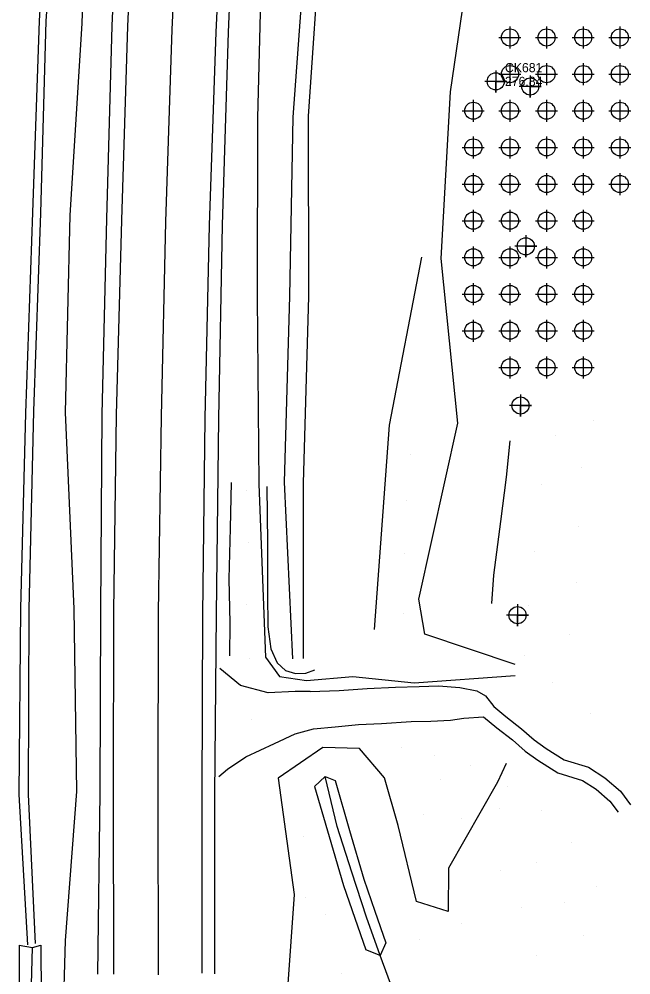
# Model space of a CAD drawing. Extents: x 1941547 to 1942851, y 663002 to 668358.
# Drawn here: x 1941926.1 to 1942093, y 667414.3 to 667675 of the extents above; entities that cross this region are included whole.
import ezdxf

# ---------------------------------------------------------------- set-up
doc = ezdxf.new("R2010")
doc.units = 0
for name, color, linetype in [('CTL GPS Vertical Cogo Elevation', 7, 'Continuous'), ('CTL NGS Vertical CELL', 7, 'Continuous'), ('Exist DTM Drainline Cogo Elevation', 7, 'Continuous'), ('Exist DTM QL2 LIDAR Elevation Point', 7, 'Continuous'), ('Exist Property Iron Pin Cogo Number', 7, 'Continuous'), ('Exist Roads EOP Cogo Point CELL', 7, 'Continuous'), ('Exist Roads EOT', 7, 'Continuous'), ('Exist Utilities Telephone UG Cable SUE LOS C Cogo Elevation', 7, 'Continuous'), ('Exist Utilities Telephone UG FO SUE LOS C Cogo Elevation', 7, 'Continuous'), ('PH Exist DTM Breakline', 7, 'Continuous'), ('PH Exist DTM Point', 7, 'Continuous')]:
    doc.layers.add(name, color=color, linetype=linetype)

msp = doc.modelspace()

# ---------------------------------------------------------------- linework, layer by layer
at = {"layer": 'CTL NGS Vertical CELL'}
for points in [[(1942024.37, 668012.57), (1942022.28, 667994.37), (1942017.39, 667944.52), (1942014.27, 667895.82), (1942009.92, 667846.63), (1942007.93, 667796.15), (1942005.97, 667746.35), (1942004.4, 667697.91), (1942000.78, 667648.26), (1941999.86, 667599.46), (1941998.39, 667548.71), (1942000.68, 667500.48)], [(1942026.8, 668012.52), (1942024.33, 667994.23), (1942019.53, 667944.62), (1942016.16, 667895.49), (1942012.43, 667846.36), (1942010.79, 667795.94), (1942008.34, 667746.43), (1942008.34, 667697.72), (1942004.96, 667648.49), (1942005.04, 667599.29), (1942003.6, 667548.44), (1942003.59, 667500.58)], [(1941930.54, 667422.84), (1941928.68, 667463.46), (1941928.78, 667514.02), (1941930.06, 667568.07), (1941931.99, 667622.09), (1941933.48, 667674.51), (1941937.26, 667726.95), (1941939.71, 667779.55), (1941943.19, 667828.89), (1941946.38, 667878.43), (1941949.61, 667928.57), (1941952.29, 667965.88), (1941953.97, 667997.88)], [(1941928.41, 667422.42), (1941926.07, 667463.45), (1941926.54, 667514.2), (1941927.95, 667567.47), (1941929.84, 667622.24), (1941931.61, 667674.49), (1941934.69, 667727.1), (1941937.88, 667779.66), (1941941.36, 667829.21), (1941944.43, 667878.58), (1941947.39, 667928.96), (1941950.55, 667966.21)]]:
    msp.add_lwpolyline(points, dxfattribs=at)
at = {"layer": 'Exist DTM Drainline Cogo Elevation'}
for points in [[(1942056.13, 667661.01), (1942056.13, 667655.01), (1942056.13, 667658.01), (1942059.13, 667658.01), (1942053.13, 667658.01)], [(1942056.13, 667661.01), (1942056.13, 667655.01), (1942056.13, 667658.01), (1942059.13, 667658.01), (1942053.13, 667658.01)], [(1942065.54, 667659.62), (1942065.54, 667653.62), (1942065.54, 667656.62), (1942068.54, 667656.62), (1942062.54, 667656.62)], [(1942064.32, 667616.02), (1942064.32, 667610.02), (1942064.32, 667613.02), (1942067.32, 667613.02), (1942061.32, 667613.02)], [(1942062.89, 667572.6), (1942062.89, 667566.6), (1942062.89, 667569.6), (1942065.89, 667569.6), (1942059.89, 667569.6)], [(1942062.08, 667515.39), (1942062.08, 667509.39), (1942062.08, 667512.39), (1942065.08, 667512.39), (1942059.08, 667512.39)]]:
    msp.add_lwpolyline(points, dxfattribs=at)
for centre in [(1942056.13, 667658.01), (1942056.13, 667658.01), (1942065.54, 667656.62), (1942064.32, 667613.02), (1942062.89, 667569.6), (1942062.08, 667512.39)]:
    msp.add_circle(centre, 2.34, dxfattribs=at)
at = {"layer": 'Exist DTM QL2 LIDAR Elevation Point'}
for points in [[(1942060, 667673), (1942060, 667670)], [(1942070, 667673), (1942070, 667670)], [(1942080, 667673), (1942080, 667670)], [(1942090, 667673), (1942090, 667670)], [(1942057, 667670), (1942060, 667670)], [(1942060, 667670), (1942063, 667670)], [(1942060, 667670), (1942060, 667667)], [(1942067, 667670), (1942070, 667670)], [(1942070, 667670), (1942073, 667670)], [(1942070, 667670), (1942070, 667667)], [(1942077, 667670), (1942080, 667670)], [(1942080, 667670), (1942083, 667670)], [(1942080, 667670), (1942080, 667667)], [(1942087, 667670), (1942090, 667670)], [(1942090, 667670), (1942093, 667670)], [(1942090, 667670), (1942090, 667667)], [(1942060, 667663), (1942060, 667660)], [(1942070, 667663), (1942070, 667660)], [(1942080, 667663), (1942080, 667660)], [(1942090, 667663), (1942090, 667660)], [(1942057, 667660), (1942060, 667660)], [(1942060, 667660), (1942063, 667660)], [(1942060, 667660), (1942060, 667657)], [(1942067, 667660), (1942070, 667660)], [(1942070, 667660), (1942073, 667660)], [(1942070, 667660), (1942070, 667657)], [(1942077, 667660), (1942080, 667660)], [(1942080, 667660), (1942083, 667660)], [(1942080, 667660), (1942080, 667657)], [(1942087, 667660), (1942090, 667660)], [(1942090, 667660), (1942093, 667660)], [(1942090, 667660), (1942090, 667657)], [(1942050, 667653), (1942050, 667650)], [(1942060, 667653), (1942060, 667650)], [(1942070, 667653), (1942070, 667650)], [(1942080, 667653), (1942080, 667650)], [(1942090, 667653), (1942090, 667650)], [(1942047, 667650), (1942050, 667650)], [(1942050, 667650), (1942053, 667650)], [(1942050, 667650), (1942050, 667647)], [(1942057, 667650), (1942060, 667650)], [(1942060, 667650), (1942063, 667650)], [(1942060, 667650), (1942060, 667647)], [(1942067, 667650), (1942070, 667650)], [(1942070, 667650), (1942073, 667650)], [(1942070, 667650), (1942070, 667647)], [(1942077, 667650), (1942080, 667650)], [(1942080, 667650), (1942083, 667650)], [(1942080, 667650), (1942080, 667647)], [(1942087, 667650), (1942090, 667650)], [(1942090, 667650), (1942093, 667650)], [(1942090, 667650), (1942090, 667647)], [(1942050, 667643), (1942050, 667640)], [(1942060, 667643), (1942060, 667640)], [(1942070, 667643), (1942070, 667640)], [(1942080, 667643), (1942080, 667640)], [(1942090, 667643), (1942090, 667640)], [(1942047, 667640), (1942050, 667640)], [(1942050, 667640), (1942053, 667640)], [(1942050, 667640), (1942050, 667637)], [(1942057, 667640), (1942060, 667640)], [(1942060, 667640), (1942063, 667640)], [(1942060, 667640), (1942060, 667637)], [(1942067, 667640), (1942070, 667640)], [(1942070, 667640), (1942073, 667640)], [(1942070, 667640), (1942070, 667637)], [(1942077, 667640), (1942080, 667640)], [(1942080, 667640), (1942083, 667640)], [(1942080, 667640), (1942080, 667637)], [(1942087, 667640), (1942090, 667640)], [(1942090, 667640), (1942093, 667640)], [(1942090, 667640), (1942090, 667637)], [(1942050, 667633), (1942050, 667630)], [(1942060, 667633), (1942060, 667630)], [(1942070, 667633), (1942070, 667630)], [(1942080, 667633), (1942080, 667630)], [(1942090, 667633), (1942090, 667630)], [(1942047, 667630), (1942050, 667630)], [(1942050, 667630), (1942053, 667630)], [(1942050, 667630), (1942050, 667627)], [(1942057, 667630), (1942060, 667630)], [(1942060, 667630), (1942063, 667630)], [(1942060, 667630), (1942060, 667627)], [(1942067, 667630), (1942070, 667630)], [(1942070, 667630), (1942073, 667630)], [(1942070, 667630), (1942070, 667627)], [(1942077, 667630), (1942080, 667630)], [(1942080, 667630), (1942083, 667630)], [(1942080, 667630), (1942080, 667627)], [(1942087, 667630), (1942090, 667630)], [(1942090, 667630), (1942093, 667630)], [(1942090, 667630), (1942090, 667627)], [(1942050, 667623), (1942050, 667620)], [(1942060, 667623), (1942060, 667620)], [(1942070, 667623), (1942070, 667620)], [(1942080, 667623), (1942080, 667620)], [(1942047, 667620), (1942050, 667620)], [(1942050, 667620), (1942053, 667620)], [(1942050, 667620), (1942050, 667617)], [(1942057, 667620), (1942060, 667620)], [(1942060, 667620), (1942063, 667620)], [(1942060, 667620), (1942060, 667617)], [(1942067, 667620), (1942070, 667620)], [(1942070, 667620), (1942073, 667620)], [(1942070, 667620), (1942070, 667617)], [(1942077, 667620), (1942080, 667620)], [(1942080, 667620), (1942083, 667620)], [(1942080, 667620), (1942080, 667617)], [(1942050, 667613), (1942050, 667610)], [(1942060, 667613), (1942060, 667610)], [(1942070, 667613), (1942070, 667610)], [(1942080, 667613), (1942080, 667610)], [(1942047, 667610), (1942050, 667610)], [(1942050, 667610), (1942053, 667610)], [(1942050, 667610), (1942050, 667607)], [(1942057, 667610), (1942060, 667610)], [(1942060, 667610), (1942063, 667610)], [(1942060, 667610), (1942060, 667607)], [(1942067, 667610), (1942070, 667610)], [(1942070, 667610), (1942073, 667610)], [(1942070, 667610), (1942070, 667607)], [(1942077, 667610), (1942080, 667610)], [(1942080, 667610), (1942083, 667610)], [(1942080, 667610), (1942080, 667607)], [(1942050, 667603), (1942050, 667600)], [(1942060, 667603), (1942060, 667600)], [(1942070, 667603), (1942070, 667600)], [(1942080, 667603), (1942080, 667600)], [(1942047, 667600), (1942050, 667600)], [(1942050, 667600), (1942053, 667600)], [(1942050, 667600), (1942050, 667597)], [(1942057, 667600), (1942060, 667600)], [(1942060, 667600), (1942063, 667600)], [(1942060, 667600), (1942060, 667597)], [(1942067, 667600), (1942070, 667600)], [(1942070, 667600), (1942073, 667600)], [(1942070, 667600), (1942070, 667597)], [(1942077, 667600), (1942080, 667600)], [(1942080, 667600), (1942083, 667600)], [(1942080, 667600), (1942080, 667597)], [(1942050, 667593), (1942050, 667590)], [(1942060, 667593), (1942060, 667590)], [(1942070, 667593), (1942070, 667590)], [(1942080, 667593), (1942080, 667590)], [(1942047, 667590), (1942050, 667590)], [(1942050, 667590), (1942053, 667590)], [(1942050, 667590), (1942050, 667587)], [(1942057, 667590), (1942060, 667590)], [(1942060, 667590), (1942063, 667590)], [(1942060, 667590), (1942060, 667587)], [(1942067, 667590), (1942070, 667590)], [(1942070, 667590), (1942073, 667590)], [(1942070, 667590), (1942070, 667587)], [(1942077, 667590), (1942080, 667590)], [(1942080, 667590), (1942083, 667590)], [(1942080, 667590), (1942080, 667587)], [(1942060, 667583), (1942060, 667580)], [(1942070, 667583), (1942070, 667580)], [(1942080, 667583), (1942080, 667580)], [(1942057, 667580), (1942060, 667580)], [(1942060, 667580), (1942063, 667580)], [(1942060, 667580), (1942060, 667577)], [(1942067, 667580), (1942070, 667580)], [(1942070, 667580), (1942073, 667580)], [(1942070, 667580), (1942070, 667577)], [(1942077, 667580), (1942080, 667580)], [(1942080, 667580), (1942083, 667580)], [(1942080, 667580), (1942080, 667577)]]:
    msp.add_lwpolyline(points, dxfattribs=at)
for centre in [(1942060, 667670), (1942070, 667670), (1942080, 667670), (1942090, 667670), (1942060, 667660), (1942070, 667660), (1942080, 667660), (1942090, 667660), (1942050, 667650), (1942060, 667650), (1942070, 667650), (1942080, 667650), (1942090, 667650), (1942050, 667640), (1942060, 667640), (1942070, 667640), (1942080, 667640), (1942090, 667640), (1942050, 667630), (1942060, 667630), (1942070, 667630), (1942080, 667630), (1942090, 667630), (1942050, 667620), (1942060, 667620), (1942070, 667620), (1942080, 667620), (1942050, 667610), (1942060, 667610), (1942070, 667610), (1942080, 667610), (1942050, 667600), (1942060, 667600), (1942070, 667600), (1942080, 667600), (1942050, 667590), (1942060, 667590), (1942070, 667590), (1942080, 667590), (1942060, 667580), (1942070, 667580), (1942080, 667580)]:
    msp.add_circle(centre, 2.34, dxfattribs=at)
at = {"layer": 'Exist Property Iron Pin Cogo Number'}
msp.add_lwpolyline([(1941986.94, 667972.46), (1941983.14, 667925.62), (1941979.11, 667875.72), (1941975.71, 667825.96), (1941972.91, 667776.76), (1941970.2, 667724.07), (1941967.78, 667672.14), (1941966.03, 667619.74), (1941964.82, 667566.56), (1941964.04, 667513.11), (1941963.9, 667463.6), (1941963.98, 667414.3)], dxfattribs=at)
at = {"layer": 'Exist Roads EOT'}
for points in [[(1941951.96, 667414.49), (1941951.82, 667463.66), (1941951.89, 667513.47), (1941952.66, 667567.03), (1941954.12, 667620.18), (1941955.74, 667673.09), (1941958.11, 667725.12), (1941960.9, 667778.05), (1941963.81, 667827.1), (1941967.02, 667877.05), (1941970.92, 667927.07), (1941974.94, 667973.32)], [(1941998.95, 667971.48), (1941994.9, 667924.27), (1941991.1, 667874.21), (1941987.79, 667824.66), (1941984.92, 667775.88), (1941982.17, 667722.97), (1941979.79, 667671.47), (1941977.97, 667618.81), (1941976.79, 667566.11), (1941976.12, 667512.58), (1941975.9, 667463.33), (1941975.97, 667414.74)]]:
    msp.add_lwpolyline(points, dxfattribs=at)
at = {"layer": 'Exist Utilities Telephone UG Cable SUE LOS C Cogo Elevation'}
for points in [[(1941947.52, 667414.49), (1941948.18, 667463.95), (1941948.33, 667513.56), (1941948.74, 667567.19), (1941950.01, 667620.48), (1941951.44, 667673.18), (1941953.79, 667725.44), (1941956.78, 667778.06), (1941959.88, 667827.56), (1941963.38, 667877.42), (1941967.24, 667927.35), (1941971.03, 667973.65)], [(1942002.64, 667971.13), (1941998.56, 667923.93), (1941994.72, 667874.07), (1941991.26, 667824.47), (1941988.15, 667775.69), (1941985.27, 667722.8), (1941983.08, 667671.41), (1941981.48, 667618.83), (1941980.44, 667566), (1941979.8, 667512.63), (1941979.4, 667463.31), (1941979.4, 667414.56)]]:
    msp.add_lwpolyline(points, dxfattribs=at)
at = {"layer": 'Exist Utilities Telephone UG FO SUE LOS C Cogo Elevation'}
for points in [[(1942015.16, 668036.81), (1942013.71, 667994.65), (1942007.92, 667945.04), (1942004.16, 667896), (1942000.03, 667846.93), (1941998.38, 667796.26), (1941995.44, 667746.75), (1941992.37, 667698.24), (1941991.14, 667648.1), (1941991.07, 667599.08), (1941991.51, 667548.12), (1941993.3, 667500.89), (1941997.12, 667495.7), (1942004.5, 667494.55), (1942017.16, 667495.67), (1942033.91, 667493.9), (1942061.43, 667495.96)], [(1941938.12, 667401.41), (1941938.73, 667423.66), (1941941.78, 667464.33), (1941941.12, 667514.11), (1941938.71, 667567.68), (1941940.02, 667621.54), (1941943.32, 667673.83), (1941944.97, 667726.11), (1941947.44, 667778.97), (1941950.62, 667828.46), (1941954.58, 667878.17), (1941957.72, 667928.48), (1941960.86, 667965.38), (1941963.56, 667974.26)], [(1942061.44, 667498.89), (1942036.78, 667507.17), (1942035.13, 667516.78), (1942045.76, 667564.8), (1942041.25, 667609.68), (1942043.79, 667655.13), (1942048.71, 667688.84), (1942047.6, 667738.81), (1942051.48, 667794.98), (1942052.88, 667842.09), (1942055.45, 667881.88)], [(1942023.03, 667508.46), (1942027.14, 667564.19), (1942035.99, 667610.1)], [(1942058.97, 667471.88), (1942056.59, 667466.81), (1942043.21, 667443.37), (1942043.12, 667431.55), (1942034.51, 667434.31), (1942029.48, 667455.03), (1942025.79, 667468.06), (1942018.93, 667476.04), (1942008.95, 667476.26), (1941996.74, 667467.91), (1942001.16, 667436.21), (1941998.43, 667397.75), (1941998.37, 667363.65), (1941997.58, 667311.94), (1941999.85, 667265.5), (1942001.89, 667214.29)]]:
    msp.add_lwpolyline(points, dxfattribs=at)
at = {"layer": 'PH Exist DTM Breakline'}
for p, q in [((1941926.08, 667422.36), (1941926.12, 667400.66)), ((1941929.21, 667400.64), (1941929.73, 667421.71)), ((1941932.03, 667422.37), (1941932.06, 667400.67))]:
    msp.add_line(p, q, dxfattribs=at)
for points in [[(1942055.1, 667515.53), (1942055.61, 667523.26), (1942057.48, 667537.91), (1942059.06, 667550.01), (1942060.06, 667559.95)], [(1941983.97, 667548.57), (1941983.64, 667536.16), (1941983.3, 667522.26), (1941983.54, 667510.18), (1941983.5, 667501.31)], [(1941993.66, 667547.48), (1941993.89, 667532.03), (1941993.84, 667518.26), (1941993.93, 667509.25), (1941994.79, 667503.23), (1941996.52, 667499.43), (1941998.79, 667497.26), (1942001.45, 667496.5), (1942004.34, 667496.6), (1942006.76, 667497.45)], [(1942005.49, 667491.61), (1942001.42, 667491.56), (1941994.02, 667491.19), (1941986.49, 667493.19), (1941980.82, 667497.87)], [(1942005.49, 667491.61), (1942013.42, 667491.83), (1942021.05, 667492.4), (1942028.75, 667492.76), (1942035.23, 667492.91), (1942040.55, 667493.12), (1942046.3, 667492.66), (1942050.93, 667491.79), (1942053.3, 667490.37), (1942055.63, 667487.46), (1942058.92, 667484.74), (1942063.17, 667481.39), (1942066.63, 667478.34), (1942069.84, 667476.06), (1942074.75, 667472.94), (1942081.44, 667470.88), (1942085.88, 667468.06), (1942090.2, 667464.34), (1942092.89, 667460.65)], [(1942006.42, 667481.42), (1942012.35, 667481.9), (1942018.69, 667482.52), (1942024.97, 667482.88), (1942033.09, 667483.38), (1942038.39, 667483.48), (1942043.82, 667483.78), (1942047.46, 667484.31), (1942052.82, 667484.69)], [(1942052.82, 667484.69), (1942056.45, 667481.69), (1942060.66, 667478.37), (1942064.19, 667475.26), (1942067.65, 667472.8), (1942073.09, 667469.35), (1942079.78, 667467.29), (1942083.53, 667464.9), (1942087.29, 667461.66), (1942089.49, 667458.65)], [(1941980.56, 667468.41), (1941982.97, 667470.37), (1941987.95, 667473.75), (1941995.73, 667477.41), (1942001.36, 667479.98), (1942006.42, 667481.42)], [(1942006.7, 667465.68), (1942009.54, 667468.41), (1942012.27, 667467.31)], [(1942024.62, 667419.53), (1942020.84, 667429.97), (1942016.85, 667442.26), (1942012.87, 667454.76), (1942009.54, 667468.41)], [(1942012.27, 667467.31), (1942016.25, 667453.66), (1942020.1, 667440.4), (1942023.12, 667431.6), (1942026.17, 667423.03)], [(1942006.7, 667465.68), (1942010.68, 667452.04), (1942014.56, 667438.65), (1942017.65, 667429.69), (1942020.7, 667421.08)], [(1942026.17, 667423.03), (1942024.62, 667419.53), (1942020.7, 667421.08)], [(1941926.08, 667422.36), (1941929.73, 667421.71), (1941932.03, 667422.37)], [(1942036.07, 667391.49), (1942031.78, 667400.13), (1942024.62, 667419.53)]]:
    msp.add_lwpolyline(points, dxfattribs=at)
at = {"layer": 'PH Exist DTM Point'}
for p, q in [((1942082.8, 667565.59), (1942082.8, 667565.59)), ((1942072.37, 667561.39), (1942072.37, 667561.39)), ((1942032.85, 667556.28), (1942032.85, 667556.28)), ((1942079.6, 667552.76), (1942079.6, 667552.76)), ((1942068.5, 667547.93), (1942068.5, 667547.93)), ((1941988.01, 667546.41), (1941988.01, 667546.41)), ((1942031.87, 667543.78), (1942031.87, 667543.78)), ((1942078.83, 667536.49), (1942078.83, 667536.49)), ((1941988.78, 667532.26), (1941988.78, 667532.26)), ((1942066.83, 667529.68), (1942066.83, 667529.68)), ((1942031.26, 667529.23), (1942031.26, 667529.23)), ((1942078.12, 667521.27), (1942078.12, 667521.27)), ((1941988.2, 667515.27), (1941988.2, 667515.27)), ((1942064.96, 667515.11), (1942064.96, 667515.11)), ((1942030.86, 667512.77), (1942030.86, 667512.77)), ((1942076.21, 667507.22), (1942076.21, 667507.22)), ((1942063.86, 667501.26), (1942063.86, 667501.26)), ((1941988.93, 667500.6), (1941988.93, 667500.6)), ((1942071.49, 667494.14), (1942071.49, 667494.14)), ((1942081.98, 667485.6), (1942081.98, 667485.6)), ((1941989.59, 667483.93), (1941989.59, 667483.93)), ((1942030.34, 667476.25), (1942030.34, 667476.25)), ((1942039.53, 667474.13), (1942039.53, 667474.13)), ((1942049.13, 667471.44), (1942049.13, 667471.44)), ((1942041.06, 667467.58), (1942041.06, 667467.58)), ((1942059.25, 667465.76), (1942059.25, 667465.76)), ((1942057.04, 667459.68), (1942057.04, 667459.68)), ((1942036.3, 667457.98), (1942036.3, 667457.98)), ((1942046.66, 667457.05), (1942046.66, 667457.05)), ((1942068.63, 667459.14), (1942068.63, 667459.14)), ((1942003.74, 667452.13), (1942003.74, 667452.13)), ((1942076.69, 667450.27), (1942076.69, 667450.27)), ((1942067.24, 667445.05), (1942067.24, 667445.05)), ((1942057.51, 667442.62), (1942057.51, 667442.62)), ((1942083.51, 667438.28), (1942083.51, 667438.28)), ((1942004.25, 667435.37), (1942004.25, 667435.37)), ((1942074.95, 667434.01), (1942074.95, 667434.01)), ((1942009.79, 667430.61), (1942009.79, 667430.61)), ((1942063.14, 667432.61), (1942063.14, 667432.61)), ((1942046.74, 667428.35), (1942046.74, 667428.35)), ((1942035.37, 667424.02), (1942035.37, 667424.02)), ((1942079.99, 667424.99), (1942079.99, 667424.99)), ((1942067.37, 667419.68), (1942067.37, 667419.68)), ((1942014.09, 667414.65), (1942014.09, 667414.65))]:
    msp.add_line(p, q, dxfattribs=at)

# ---------------------------------------------------------------- texts
at = {"layer": 'CTL GPS Vertical Cogo Elevation'}
msp.add_text('CK681', height=2.5, dxfattribs=at).set_placement((1942058.63, 667660.51))
at = {"layer": 'Exist Roads EOP Cogo Point CELL'}
msp.add_text('276.84', height=2.5, dxfattribs=at).set_placement((1942058.63, 667656.76))

doc.saveas('drawing.dxf')
